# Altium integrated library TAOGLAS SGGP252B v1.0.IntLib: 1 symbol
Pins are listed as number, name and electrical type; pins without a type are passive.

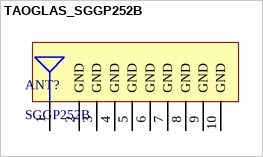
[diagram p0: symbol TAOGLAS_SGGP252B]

## TAOGLAS_SGGP252B
designator ANT?, comment SGGP252B
GPS/GLONASS/GALILEO Dual-Band 25*25*2mm Ceramic Patch SMD Antenna; ComponentLibStatus: Created; MFG: Taoglas; Temp_High: +85C; Temp_Low: -40C
footprint TAOGLAS_SGGP252B (GPS/GLONASS/GALILEO Dual-Band 25*25*2mm Ceramic Patch SMD Antenna)
pins: 1 RF FEED, 2 GND, 3 GND, 4 GND, 5 GND, 6 GND, 7 GND, 8 GND, 9 GND, 10 GND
